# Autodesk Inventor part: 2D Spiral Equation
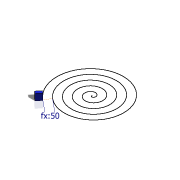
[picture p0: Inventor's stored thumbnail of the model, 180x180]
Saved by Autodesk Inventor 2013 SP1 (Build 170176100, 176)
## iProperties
Created: 2012-12
Part Number: 2D Spiral Equation
Material: Generic
Document SubType Name: Modeling
Designer: luke.davenport
Density: 0.001 g/cm^3
Mass: 0.0382322 g
Surface Area: 72.7657 cm^2
Volume: 38.2322 cm^3
RuleStatus: InUse
AfterDocOpen0: Show Form
Author: luke.davenport
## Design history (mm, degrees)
sketch "Sketch3"
  geometry: L1 (152.069, 198.564)-(120.42, 159.856); 7 further points; 3 other entities
  constraints: 3 coincident, 2 end point, 18 other
  dimensions: "d8" = 50 distance of L1.start L1.end (= Spacing)
  node "2D Equation Curve1" dims "d0" = 0, "d1" = 18000 (= 360 x Rotations)
sketch "Sketch4"
  geometry: L1 (152.069, 198.564)-(164.948, 213.912); L2 (159.962, 191.987)-(144.221, 205.196); L3 (144.221, 205.196)-(169.933, 235.838); L4 (169.933, 235.838)-(185.675, 222.628); L5 (185.675, 222.628)-(159.962, 191.987); L6 (159.962, 191.987)-(169.933, 235.838); L7 (144.221, 205.196)-(185.675, 222.628); 1 further point
  constraints: 14 end point, 2 midpoint, 2 parallel, 2 perpendicular
  dimensions: "d15" = 40 distance of L4.end L2.start
extrude "Extrusion2" new body sketch "Sketch4" distance "d17" = 46.5125; taper "d18" = 0 deg
body "Solid2"
other parameters: "Spacing_Calc" = 0.13895 (= 0.00277895 x Spacing) [user parameter], "Spacing" = 50 [user parameter; used in 2 equation terms]
